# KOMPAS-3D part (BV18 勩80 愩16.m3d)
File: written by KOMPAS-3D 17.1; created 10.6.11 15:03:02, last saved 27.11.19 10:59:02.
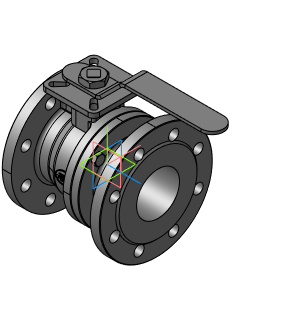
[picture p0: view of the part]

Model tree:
1. Плоскость XY
2. Плоскость ZX
3. Плоскость ZY
4. Ось X
5. Ось Y
6. Ось Z
7. Начало координат
8. Операция без истории:8

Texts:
  Толщина листового тела
  Глубина освобождения сгиба
  Ширина освобождения сгиба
